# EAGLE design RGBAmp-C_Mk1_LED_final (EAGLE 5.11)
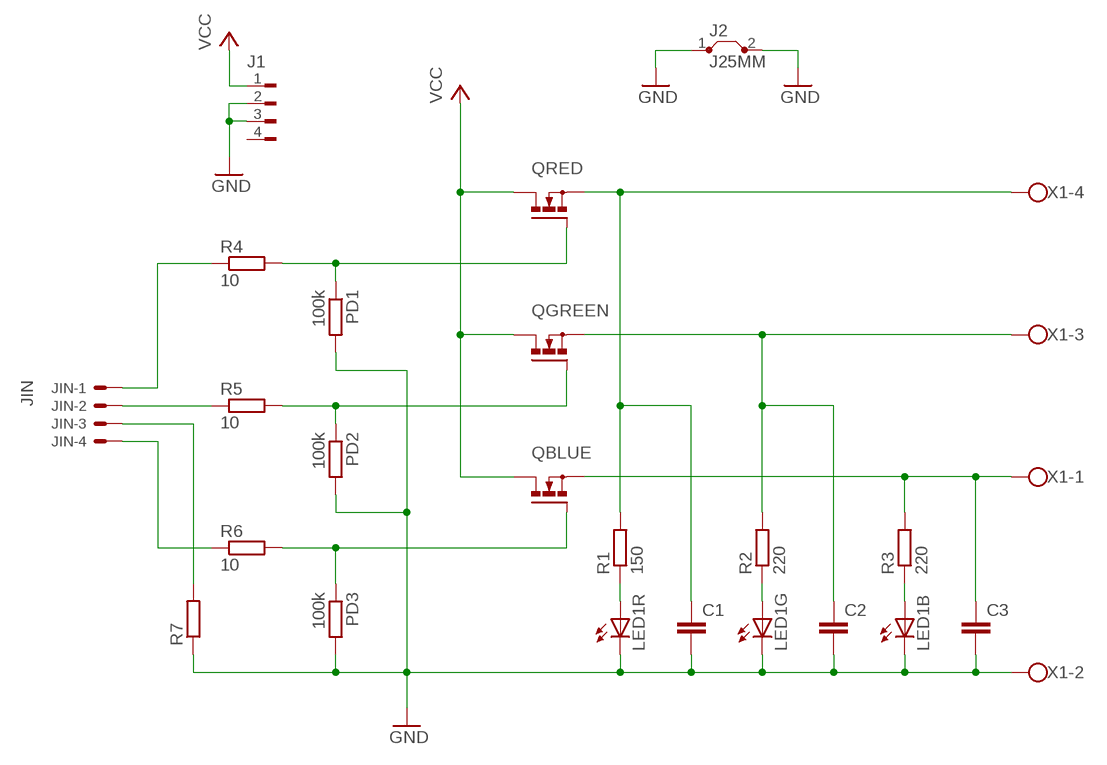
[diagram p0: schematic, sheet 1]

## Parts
C1  C2,5-3  [C2.5-3]
C2  C2,5-3  [C2.5-3]
C3  C2,5-3  [C2.5-3]
J1  FLOPPY-4  [FLOPPY-4]
J2  J25MM  [25]
JIN  JIN  22--04  [6410-04A]
LED1  MULTILED_LRTB_G6TG  [P-LCC-6_TOPLED]
PD1  100k  R-EU_0207/5V  [0207/5V]
PD2  100k  R-EU_0204/7  [0204/7]
PD3  100k  R-EU_0207/5V  [0207/5V]
QBLUE  PMOSFET_NTO220BV  [TO220BV]
QGREEN  PMOSFET_NTO220BV  [TO220BV]
QRED  PMOSFET_NTO220BV  [TO220BV]
R1  150  R-EU_0207/2V  [0207/2V]
R2  220  R-EU_0207/12  [0207/12]
R3  220  R-EU_0207/15  [0207/15]
R4  10  R-EU_0207/5V  [0207/5V]
R5  10  R-EU_0207/5V  [0207/5V]
R6  10  R-EU_0207/2V  [0207/2V]
R7  R-EU_0207/5V  [0207/5V]
X1  W237-4  [W237-4]

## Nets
GND: C1.2 C2.2 C3.2 J1.2 J1.3 J2.1 J2.2 LED1.C1(R:C) LED1.C2(G:C) LED1.C3(B:C) PD1.2 PD2.2 PD3.2 R7.1 X1.2
N$1: PD1.1 QRED.G R4.2
N$2: PD2.1 QGREEN.G R5.2
N$3: PD3.1 QBLUE.G R6.2
N$4: JIN.4 R6.1
N$5: JIN.1 R4.1
N$6: JIN.2 R5.1
N$7: C1.1 QRED.S R1.2 X1.4
N$8: C2.1 QGREEN.S R2.2 X1.3
N$9: C3.1 QBLUE.S R3.2 X1.1
N$10: LED1.A1(R:A) R1.1
N$11: LED1.A2(G:A) R2.1
N$12: LED1.A3(B:A) R3.1
N$13: JIN.3 R7.2
VCC: J1.1 QBLUE.D QGREEN.D QRED.D
Unconnected: J1.4

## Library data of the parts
C1-C3 = capacitor-wima:C: CAPACITOR
J1 = con-amp:FLOPPY-4: MATE N-LOCK Floppy / HDD conector Distributor: Bürklin 71F970; OC_FARNELL: unknown; OC_NEWARK: unknown
J2 = jumper:J: Bridge
JIN = con-molex:22-?-04: CONNECTOR wire to board 2.54 mm (.1 inch) pitch header
LED1 = led:MULTILED_LRTB_G6TG: 6-lead MULTILED® Enhanced optical Power LED (ThinFilm® / ThinGaN®) Source. OSRAM - LRTB_G6TG.pdf
PD1-PD3 = resistor:R-EU_: RESISTOR, European symbol
QBLUE QGREEN QRED = transistor-power:PMOSFET_N: Power MOSFET N-Channel
R1-R7 = rcl:R-EU_: RESISTOR, European symbol
X1 = con-wago-500:W237-4: WAGO SCREW CLAMP; OC_FARNELL: unknown; OC_NEWARK: unknown

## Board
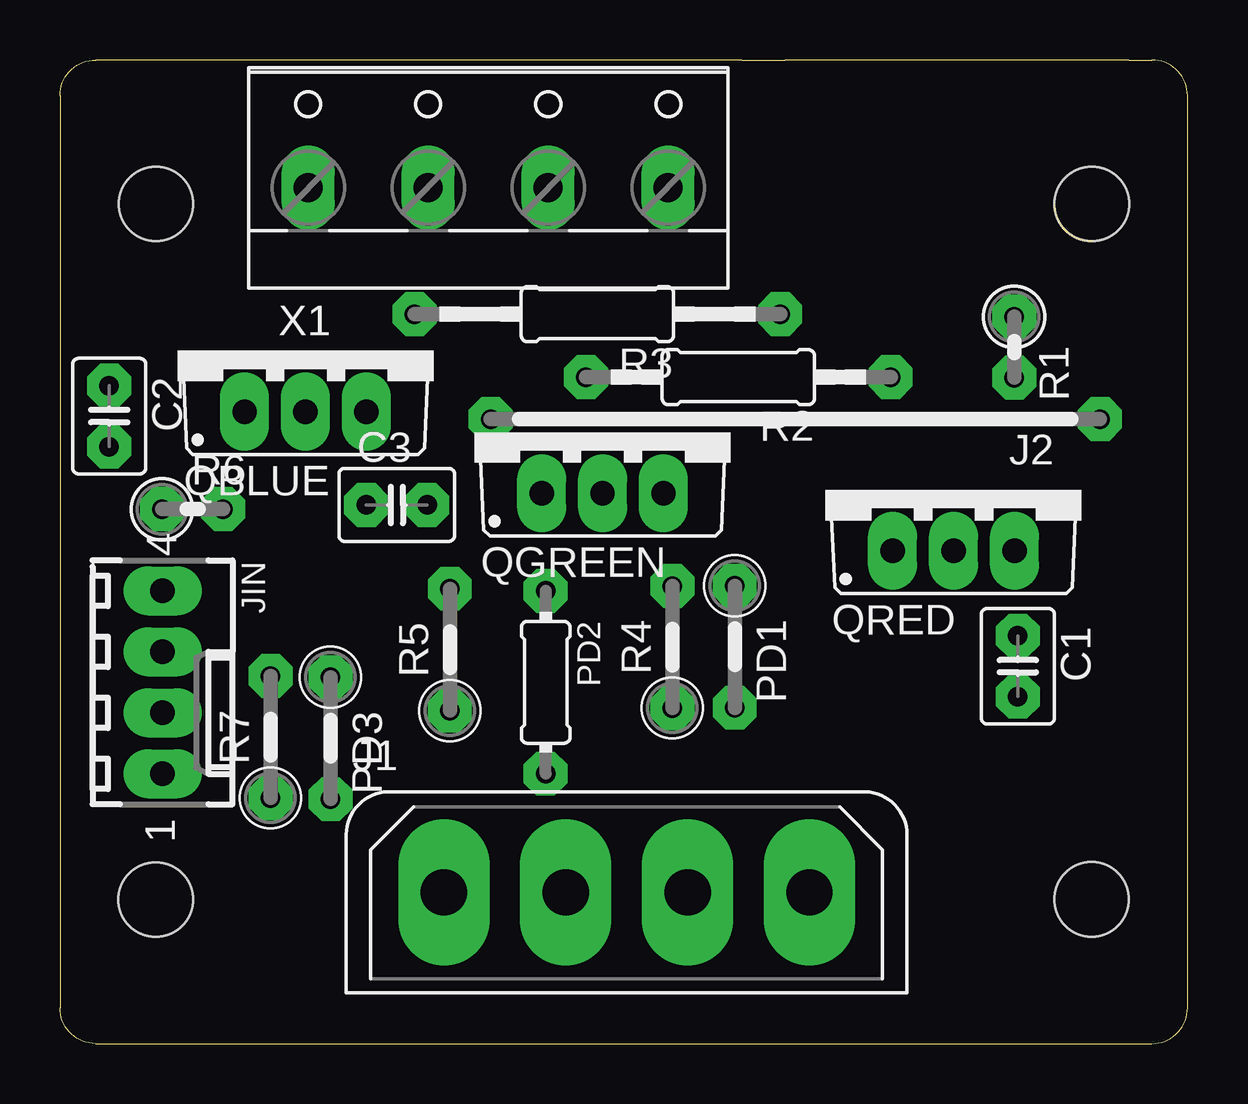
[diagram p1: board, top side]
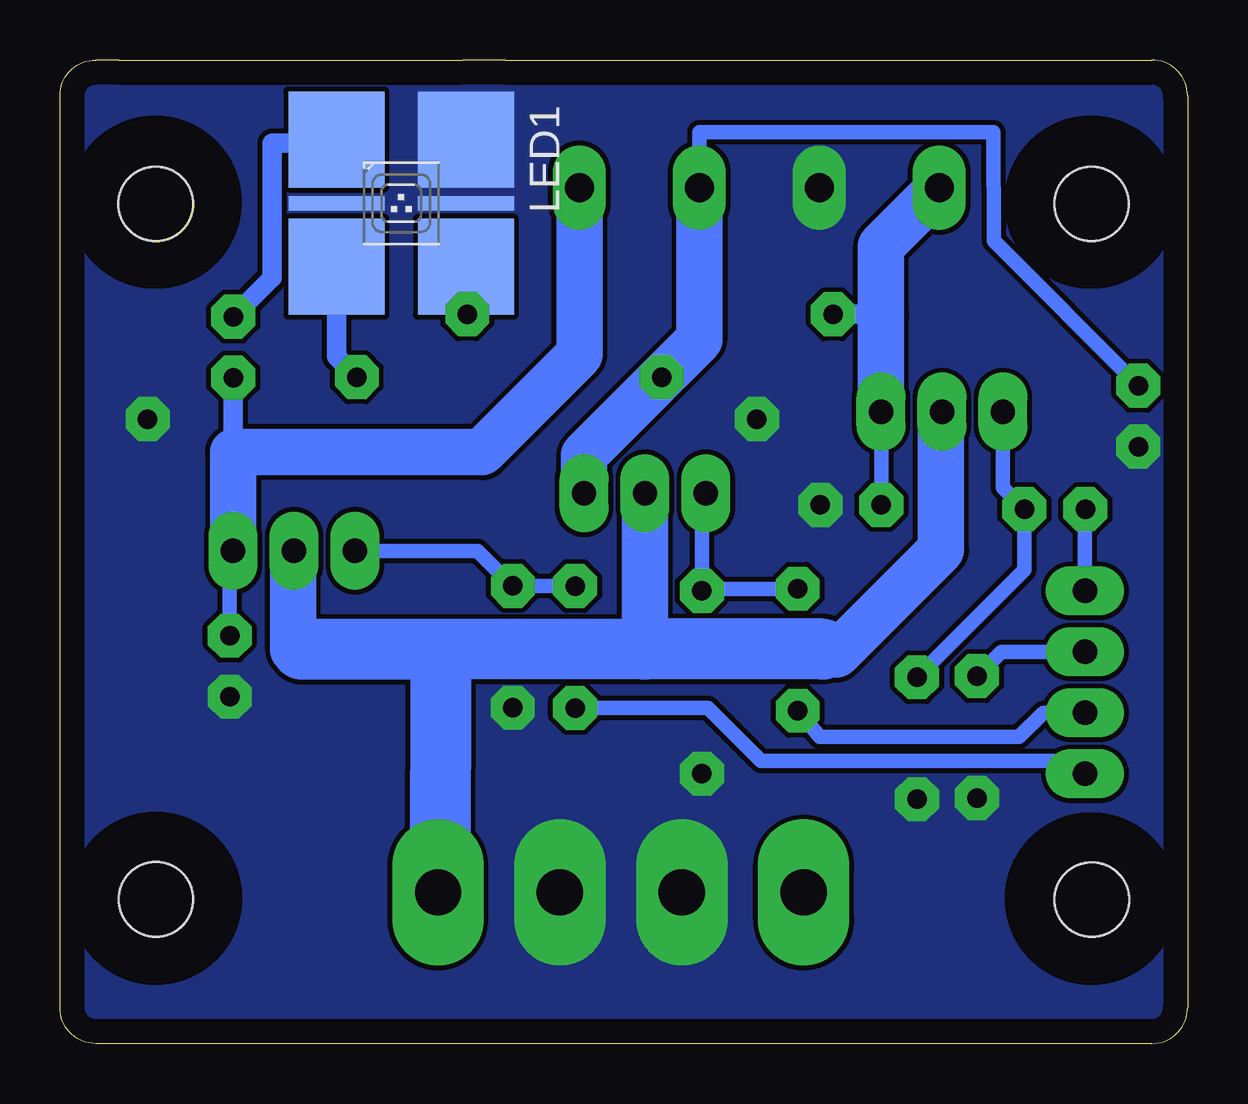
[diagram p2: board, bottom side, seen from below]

Size 47 x 41 mm. Coordinates in mm from the lower left corner, seen from the top.
Outline: 41.44,35.03 arc90 43.02,33.45 43.03,33.45
Outline: 44.55,41 45.51,41 arc-90 47,39.51 47,1.49 arc-90 45.51,0 1.49,0 arc-90 0,1.49 0,39.51 arc-90 1.49,41 28.43,41 30.21,41 44.55,41
Copper layers (1*16): Top 0.035mm / dielectric 1.5mm / Bottom 0.035mm
Design rules "default *": minimum track width 10mil, minimum drill 24mil, track to track 8mil, track to pad 8mil, pad to pad 8mil, via to via 8mil, smd to smd 8mil, copper to edge 40mil, drill to drill 8mil, minimum pad ring 20mil, minimum via ring 8mil, stop-mask expansion 4mil, vias tented up to drill 0mil, thermal gap 10mil
Holes 3.1 mm at 43,6.01 3.99,6 4,35 43.01,35
bKeepout: area 39.4,2.5 to 46.6,9.7; area 39.4,31.5 to 46.6,38.7; area 0.4,2.5 to 7.6,9.7; area 0.4,31.5 to 7.6,38.7
tRestrict: area 39.5,31.5 to 46.7,38.7; area 39.4,2.5 to 46.6,9.7; area 0.5,31.5 to 7.7,38.7; area 0.4,2.5 to 7.6,9.7
bRestrict: area 39.4,2.4 to 46.6,9.6; area 39.4,31.5 to 46.6,38.7; area 0.4,2.4 to 7.6,9.6; area 0.4,31.5 to 7.6,38.7

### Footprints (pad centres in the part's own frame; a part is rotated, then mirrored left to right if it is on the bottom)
C2.5-3 = drill 0.813 pad 1.6 octagon: 1 -1.27,0; 2 1.27,0
FLOPPY-4 = drill 1.93 pad 3.81 long: 1 7.62,0; 2 2.54,0; 3 -2.54,0; 4 -7.62,0
25 = drill 0.813 pad 1.6 octagon: 1 -12.7,0; 2 12.7,0
6410-04A = drill 1.016 long: 1 3.81,0; 2 1.27,0; 3 -1.27,0; 4 -3.81,0
P-LCC-6_TOPLED = smd 4 x 4: A1 -2.65,-2.7; A2 2.65,-2.7; A3 2.65,2.7; C1 -2.65,2.7 | smd 0.6 x 4: C2 0,-2.7; C3 0,2.7
0207/5V = drill 0.813 octagon: 1 -2.54,0; 2 2.54,0
0204/7 = drill 0.813 octagon: 1 -3.81,0; 2 3.81,0
TO220BV = drill 1.016 long: D 0,-2.54; G -2.54,-2.54; S 2.54,-2.54
0207/2V = drill 0.813 octagon: 1 -1.27,0; 2 1.27,0
0207/12 = drill 0.813 octagon: 1 -6.35,0; 2 6.35,0
0207/15 = drill 0.813 octagon: 1 -7.62,0; 2 7.62,0
W237-4 = drill 1.194 long: 1 -7.5,-1.27; 2 -2.5,-1.27; 3 2.5,-1.27; 4 7.5,-1.27

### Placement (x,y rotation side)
C1  39.93,15.73 270 top
C2  2.05,26.15 270 top
C3  14.04,22.45 0 top
J1  23.62,6.3 0 top
J2  30.65,26.03 180 top
JIN  4.28,15.06 270 top
LED1  32.78,35.03 270 bottom
PD1  28.13,16.54 270 top
PD2  20.25,15.06 270 top
PD3  11.28,12.73 270 top
QBLUE  10.24,28.88 0 top
QGREEN  22.62,25.48 0 top
QRED  37.25,23.08 0 top
R1  39.78,29.03 270 top
R2  28.28,27.78 180 top
R3  22.4,30.4 180 top
R4  25.53,16.53 90 top
R5  16.25,16.42 90 top
R6  5.53,22.28 0 top
R7  8.78,12.78 90 top
X1  17.85,36.95 0 top

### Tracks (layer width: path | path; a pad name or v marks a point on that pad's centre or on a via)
GND
  pour Bottom (no thermals): 0.28,39.53 1.53,40.78 45.53,40.78 46.78,39.53 46.78,1.53 45.53,0.28 1.53,0.28 0.28,1.53
N$1
  Bottom 0.61: R4.2 PD1.1 29.59,20.54 QRED.G
N$2
  Bottom 0.61: R5.2 20.2,18.96 PD2.1 20.25,22.77 QGREEN.G
N$3
  Bottom 0.61: QBLUE.G 7.7,23.18 R6.2 6.8,19.75 PD3.1
N$4
  Bottom 0.61: JIN.4 4.28,22.26 R6.1
N$5
  Bottom 0.61: R4.1 19.99,13.99 17.78,11.78 4.87,11.78 4.34,11.25 JIN.1
N$6
  Bottom 0.61: R5.1 15.32,12.78 7.03,12.78 6.02,13.79 JIN.2
N$7
  Bottom 0.61: QRED.S 39.93,20.54 C1.1
  Bottom 0.813: 39.79,24.65 39.78,24.66 R1.2
  Bottom 1.93: QRED.S 39.79,24.65 29.4,24.65 25.35,28.71 X1.4
N$8
  Bottom 0.61: R2.2 22.01,27.7 22.01,27.67 | C2.1 8.08,33.47 8.1,37.99 20.35,37.99 X1.3
  Bottom 1.93: QGREEN.S 25.16,24.52 22.01,27.67 20.35,29.33 X1.3
N$9
  Bottom 0.61: QBLUE.S C3.1
  Bottom 0.813: 12.78,30.4 R3.2
  Bottom 1.93: QBLUE.S 12.78,30.4 12.78,33.25 X1.1
N$10
  Bottom 0.813: 35.63,37.53 38.15,37.53 38.15,31.92 R1.1
  Bottom 1.93: 35.63,37.53 LED1.A1
N$11
  Bottom 0.813: R2.1 35.48,28.63 LED1.A2
N$12
  Bottom 0.813: R3.1 30.08,30.46 LED1.A3
N$13
  Bottom 0.61: JIN.3 7.77,16.33 R7.2
VCC
  Bottom 1.93: 22.62,16.44 QGREEN.D | QRED.D 37.28,20.54 37.28,16.4 35.51,16.43 | QBLUE.D 10.28,26.34 10.28,20.58 14.64,16.22 14.89,16.22 15.2,16.44
  Bottom 2.54: 31.14,16.43 22.62,16.44 15.2,16.44 | 31.14,16.43 35.51,16.43 36.91,16.43 | J1.1 31.15,6.39 31.14,16.43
